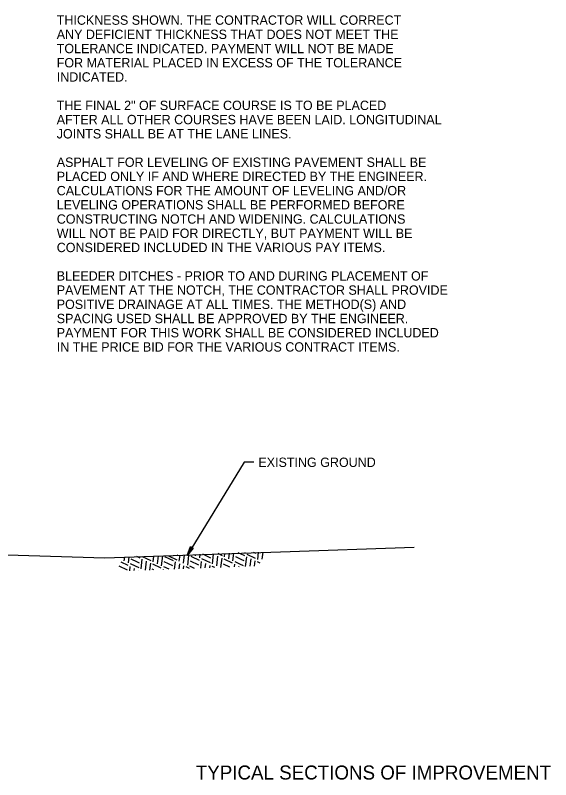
# Model space of a CAD drawing. Extents: x 1824008 to 1828864, y 689441 to 689870.
# Drawn here: x 1828827.02 to 1828861.38, y 689770.93 to 689820.02 of the extents above; entities that cross this region are included whole.
import ezdxf

# ---------------------------------------------------------------- set-up
doc = ezdxf.new("R2010")
doc.units = 0
for name, color, linetype in [('1', 7, 'Continuous'), ('19', 7, 'Continuous'), ('R_Draft', 7, 'Continuous')]:
    doc.layers.add(name, color=color, linetype=linetype)

msp = doc.modelspace()

# ---------------------------------------------------------------- linework, layer by layer
at = {"layer": '1'}
for p, q in [((1828839.673, 689784.783), (1828839.749, 689785.411)), ((1828839.673, 689784.783), (1828839.749, 689785.411)), ((1828840.31, 689785.311), (1828840.03, 689785.444)), ((1828840.31, 689785.311), (1828840.03, 689785.444)), ((1828840.31, 689785.311), (1828840.03, 689785.444)), ((1828840.446, 689785.247), (1828840.472, 689785.46)), ((1828840.446, 689785.247), (1828840.472, 689785.46)), ((1828840.446, 689785.247), (1828840.472, 689785.46)), ((1828840.717, 689785.118), (1828840.76, 689785.471)), ((1828840.717, 689785.118), (1828840.76, 689785.471)), ((1828840.717, 689785.118), (1828840.76, 689785.471)), ((1828840.988, 689784.99), (1828841.048, 689785.481)), ((1828840.988, 689784.99), (1828841.048, 689785.481)), ((1828840.988, 689784.99), (1828841.048, 689785.481)), ((1828841.697, 689785.318), (1828841.331, 689785.492)), ((1828841.697, 689785.318), (1828841.331, 689785.492)), ((1828841.697, 689785.318), (1828841.331, 689785.492)), ((1828841.761, 689785.454), (1828841.768, 689785.508)), ((1828841.761, 689785.454), (1828841.768, 689785.508)), ((1828841.761, 689785.454), (1828841.768, 689785.508)), ((1828842.477, 689785.447), (1828842.306, 689785.528)), ((1828842.477, 689785.447), (1828842.306, 689785.528)), ((1828842.477, 689785.447), (1828842.306, 689785.528)), ((1828842.574, 689785.069), (1828842.631, 689785.54)), ((1828842.574, 689785.069), (1828842.631, 689785.54)), ((1828842.574, 689785.069), (1828842.631, 689785.54)), ((1828842.863, 689785.086), (1828842.919, 689785.55)), ((1828842.863, 689785.086), (1828842.919, 689785.55)), ((1828842.863, 689785.086), (1828842.919, 689785.55)), ((1828834.01, 689784.976), (1828834.04, 689785.222)), ((1828834.01, 689784.976), (1828834.04, 689785.222)), ((1828834.01, 689784.976), (1828834.04, 689785.222)), ((1828834.281, 689784.847), (1828834.328, 689785.233)), ((1828834.281, 689784.847), (1828834.328, 689785.233)), ((1828834.281, 689784.847), (1828834.328, 689785.233)), ((1828834.862, 689784.904), (1828834.455, 689785.097)), ((1828834.862, 689784.904), (1828834.455, 689785.097)), ((1828834.862, 689784.904), (1828834.455, 689785.097)), ((1828834.99, 689785.176), (1828834.83, 689785.252)), ((1828834.99, 689785.176), (1828834.83, 689785.252)), ((1828834.99, 689785.176), (1828834.83, 689785.252)), ((1828835.035, 689785.154), (1828834.99, 689785.176)), ((1828835.035, 689785.154), (1828834.99, 689785.176)), ((1828835.035, 689785.154), (1828834.99, 689785.176)), ((1828835.095, 689784.462), (1828835.171, 689785.09)), ((1828835.095, 689784.462), (1828835.171, 689785.09)), ((1828835.095, 689784.462), (1828835.171, 689785.09)), ((1828835.732, 689784.99), (1828835.19, 689785.247)), ((1828835.732, 689784.99), (1828835.19, 689785.247)), ((1828835.732, 689784.99), (1828835.19, 689785.247)), ((1828835.372, 689784.384), (1828835.442, 689784.962)), ((1828835.372, 689784.384), (1828835.442, 689784.962)), ((1828835.372, 689784.384), (1828835.442, 689784.962)), ((1828835.868, 689784.926), (1828835.912, 689785.292)), ((1828835.868, 689784.926), (1828835.912, 689785.292)), ((1828835.868, 689784.926), (1828835.912, 689785.292)), ((1828836.139, 689784.797), (1828836.2, 689785.302)), ((1828836.139, 689784.797), (1828836.2, 689785.302)), ((1828836.139, 689784.797), (1828836.2, 689785.302)), ((1828836.41, 689784.669), (1828836.486, 689785.297)), ((1828836.41, 689784.669), (1828836.486, 689785.297)), ((1828836.41, 689784.669), (1828836.486, 689785.297)), ((1828837.164, 689784.976), (1828836.622, 689785.233)), ((1828837.164, 689784.976), (1828836.622, 689785.233)), ((1828837.164, 689784.976), (1828836.622, 689785.233)), ((1828837.409, 689785.026), (1828836.867, 689785.283)), ((1828837.409, 689785.026), (1828836.867, 689785.283)), ((1828837.409, 689785.026), (1828836.867, 689785.283)), ((1828837.447, 689785.34), (1828837.43, 689785.348)), ((1828837.447, 689785.34), (1828837.43, 689785.348)), ((1828837.447, 689785.34), (1828837.43, 689785.348)), ((1828837.544, 689784.962), (1828837.592, 689785.354)), ((1828837.544, 689784.962), (1828837.592, 689785.354)), ((1828837.544, 689784.962), (1828837.592, 689785.354)), ((1828837.815, 689784.833), (1828837.88, 689785.364)), ((1828837.815, 689784.833), (1828837.88, 689785.364)), ((1828837.815, 689784.833), (1828837.88, 689785.364)), ((1828838.087, 689784.705), (1828838.163, 689785.333)), ((1828838.087, 689784.705), (1828838.163, 689785.333)), ((1828838.087, 689784.705), (1828838.163, 689785.333)), ((1828838.802, 689784.698), (1828838.26, 689784.954)), ((1828838.802, 689784.698), (1828838.26, 689784.954)), ((1828838.802, 689784.698), (1828838.26, 689784.954)), ((1828838.343, 689785.247), (1828838.298, 689785.268)), ((1828838.343, 689785.247), (1828838.298, 689785.268)), ((1828838.343, 689785.247), (1828838.298, 689785.268)), ((1828838.84, 689785.011), (1828838.343, 689785.247)), ((1828838.84, 689785.011), (1828838.343, 689785.247)), ((1828838.84, 689785.011), (1828838.343, 689785.247)), ((1828838.588, 689785.297), (1828838.6, 689785.391)), ((1828838.588, 689785.297), (1828838.6, 689785.391)), ((1828838.588, 689785.297), (1828838.6, 689785.391)), ((1828838.859, 689785.168), (1828838.888, 689785.401)), ((1828838.859, 689785.168), (1828838.888, 689785.401)), ((1828838.859, 689785.168), (1828838.888, 689785.401)), ((1828838.924, 689784.515), (1828838.976, 689784.947)), ((1828838.924, 689784.515), (1828838.976, 689784.947)), ((1828838.924, 689784.515), (1828838.976, 689784.947)), ((1828839.537, 689784.847), (1828838.995, 689785.104)), ((1828839.537, 689784.847), (1828838.995, 689785.104)), ((1828839.537, 689784.847), (1828838.995, 689785.104)), ((1828839.575, 689785.161), (1828839.055, 689785.408)), ((1828839.575, 689785.161), (1828839.055, 689785.408)), ((1828839.575, 689785.161), (1828839.055, 689785.408)), ((1828839.944, 689784.655), (1828840.02, 689785.283)), ((1828839.944, 689784.655), (1828840.02, 689785.283)), ((1828839.944, 689784.655), (1828840.02, 689785.283)), ((1828840.22, 689784.563), (1828840.291, 689785.154)), ((1828840.22, 689784.563), (1828840.291, 689785.154)), ((1828840.22, 689784.563), (1828840.291, 689785.154)), ((1828840.969, 689784.833), (1828840.427, 689785.09)), ((1828840.969, 689784.833), (1828840.427, 689785.09)), ((1828840.969, 689784.833), (1828840.427, 689785.09)), ((1828841.44, 689784.776), (1828841.124, 689784.926)), ((1828841.44, 689784.776), (1828841.124, 689784.926)), ((1828841.44, 689784.776), (1828841.124, 689784.926)), ((1828841.568, 689785.047), (1828841.162, 689785.24)), ((1828841.568, 689785.047), (1828841.162, 689785.24)), ((1828841.568, 689785.047), (1828841.162, 689785.24)), ((1828841.704, 689784.983), (1828841.568, 689785.047)), ((1828841.704, 689784.983), (1828841.568, 689785.047)), ((1828841.704, 689784.983), (1828841.568, 689785.047)), ((1828841.742, 689785.297), (1828841.697, 689785.318)), ((1828841.742, 689785.297), (1828841.697, 689785.318)), ((1828841.742, 689785.297), (1828841.697, 689785.318)), ((1828841.803, 689784.621), (1828841.878, 689785.233)), ((1828841.803, 689784.621), (1828841.878, 689785.233)), ((1828841.803, 689784.621), (1828841.878, 689785.233)), ((1828842.439, 689785.133), (1828841.897, 689785.39)), ((1828842.439, 689785.133), (1828841.897, 689785.39)), ((1828842.439, 689785.133), (1828841.897, 689785.39)), ((1828842.091, 689784.632), (1828842.149, 689785.104)), ((1828842.091, 689784.632), (1828842.149, 689785.104)), ((1828842.091, 689784.632), (1828842.149, 689785.104)), ((1828842.379, 689784.642), (1828842.42, 689784.976)), ((1828842.379, 689784.642), (1828842.42, 689784.976)), ((1828842.379, 689784.642), (1828842.42, 689784.976)), ((1828834.224, 689784.376), (1828833.686, 689784.631)), ((1828834.224, 689784.376), (1828833.686, 689784.631)), ((1828834.224, 689784.376), (1828833.686, 689784.631)), ((1828834.262, 689784.69), (1828833.815, 689784.902)), ((1828834.262, 689784.69), (1828833.815, 689784.902)), ((1828834.262, 689784.69), (1828833.815, 689784.902)), ((1828834.364, 689784.346), (1828834.398, 689784.626)), ((1828834.364, 689784.346), (1828834.398, 689784.626)), ((1828834.364, 689784.346), (1828834.398, 689784.626)), ((1828834.733, 689784.633), (1828834.417, 689784.783)), ((1828834.733, 689784.633), (1828834.417, 689784.783)), ((1828834.733, 689784.633), (1828834.417, 689784.783)), ((1828834.652, 689784.357), (1828834.669, 689784.498)), ((1828834.652, 689784.357), (1828834.669, 689784.498)), ((1828834.652, 689784.357), (1828834.669, 689784.498)), ((1828834.959, 689784.526), (1828834.733, 689784.633)), ((1828834.959, 689784.526), (1828834.733, 689784.633)), ((1828834.959, 689784.526), (1828834.733, 689784.633)), ((1828834.997, 689784.84), (1828834.862, 689784.904)), ((1828834.997, 689784.84), (1828834.862, 689784.904)), ((1828834.997, 689784.84), (1828834.862, 689784.904)), ((1828835.66, 689784.394), (1828835.713, 689784.833)), ((1828835.66, 689784.394), (1828835.713, 689784.833)), ((1828835.66, 689784.394), (1828835.713, 689784.833)), ((1828835.918, 689784.404), (1828835.811, 689784.455)), ((1828835.918, 689784.404), (1828835.811, 689784.455)), ((1828835.918, 689784.404), (1828835.811, 689784.455)), ((1828836.391, 689784.512), (1828835.849, 689784.769)), ((1828836.391, 689784.512), (1828835.849, 689784.769)), ((1828836.391, 689784.512), (1828835.849, 689784.769)), ((1828836.524, 689784.426), (1828836.526, 689784.448)), ((1828836.524, 689784.426), (1828836.526, 689784.448)), ((1828836.524, 689784.426), (1828836.526, 689784.448)), ((1828836.894, 689784.44), (1828836.545, 689784.605)), ((1828836.894, 689784.44), (1828836.545, 689784.605)), ((1828836.894, 689784.44), (1828836.545, 689784.605)), ((1828837.126, 689784.662), (1828836.583, 689784.919)), ((1828837.126, 689784.662), (1828836.583, 689784.919)), ((1828837.126, 689784.662), (1828836.583, 689784.919)), ((1828837.244, 689784.453), (1828837.299, 689784.912)), ((1828837.244, 689784.453), (1828837.299, 689784.912)), ((1828837.244, 689784.453), (1828837.299, 689784.912)), ((1828837.532, 689784.463), (1828837.57, 689784.783)), ((1828837.532, 689784.463), (1828837.57, 689784.783)), ((1828837.532, 689784.463), (1828837.57, 689784.783)), ((1828837.82, 689784.474), (1828837.842, 689784.655)), ((1828837.82, 689784.474), (1828837.842, 689784.655)), ((1828837.82, 689784.474), (1828837.842, 689784.655)), ((1828838.022, 689784.569), (1828837.977, 689784.591)), ((1828838.022, 689784.569), (1828837.977, 689784.591)), ((1828838.022, 689784.569), (1828837.977, 689784.591)), ((1828838.194, 689784.488), (1828838.022, 689784.569)), ((1828838.194, 689784.488), (1828838.022, 689784.569)), ((1828838.194, 689784.488), (1828838.022, 689784.569)), ((1828838.519, 689784.5), (1828838.222, 689784.64)), ((1828838.519, 689784.5), (1828838.222, 689784.64)), ((1828838.519, 689784.5), (1828838.222, 689784.64)), ((1828839.212, 689784.525), (1828839.247, 689784.819)), ((1828839.212, 689784.525), (1828839.247, 689784.819)), ((1828839.212, 689784.525), (1828839.247, 689784.819)), ((1828839.5, 689784.536), (1828839.518, 689784.69)), ((1828839.5, 689784.536), (1828839.518, 689784.69)), ((1828839.5, 689784.536), (1828839.518, 689784.69)), ((1828839.819, 689784.548), (1828839.654, 689784.626)), ((1828839.819, 689784.548), (1828839.654, 689784.626)), ((1828839.819, 689784.548), (1828839.654, 689784.626)), ((1828840.794, 689784.584), (1828840.389, 689784.776)), ((1828840.794, 689784.584), (1828840.389, 689784.776)), ((1828840.794, 689784.584), (1828840.389, 689784.776)), ((1828841.083, 689784.595), (1828841.105, 689784.769)), ((1828841.083, 689784.595), (1828841.105, 689784.769)), ((1828841.083, 689784.595), (1828841.105, 689784.769)), ((1828841.371, 689784.605), (1828841.376, 689784.64)), ((1828841.371, 689784.605), (1828841.376, 689784.64)), ((1828841.371, 689784.605), (1828841.376, 689784.64)), ((1828841.666, 689784.669), (1828841.44, 689784.776)), ((1828841.666, 689784.669), (1828841.44, 689784.776)), ((1828841.666, 689784.669), (1828841.44, 689784.776)), ((1828842.739, 689784.824), (1828842.555, 689784.912)), ((1828842.739, 689784.824), (1828842.555, 689784.912)), ((1828842.739, 689784.824), (1828842.555, 689784.912)), ((1828834.94, 689784.368), (1828834.94, 689784.369)), ((1828834.94, 689784.368), (1828834.94, 689784.369)), ((1828834.94, 689784.368), (1828834.94, 689784.369))]:
    msp.add_line(p, q, dxfattribs=at)
msp.add_lwpolyline([(1828852.627, 689785.831), (1828844.044, 689785.542), (1828832.759, 689785.156), (1828826.49, 689785.349), (1828820.607, 689784.963), (1828817.941, 689784.736)], dxfattribs=at)
at = {"layer": 'R_Draft'}
for p, q in [((1828838.042, 689785.336), (1828838.265, 689785.903)), ((1828838.265, 689785.903), (1828838.443, 689785.793)), ((1828838.443, 689785.793), (1828838.042, 689785.336)), ((1828838.116, 689785.477), (1828838.309, 689785.871)), ((1828838.402, 689785.815), (1828838.139, 689785.466)), ((1828839.673, 689784.783), (1828839.749, 689785.411)), ((1828840.31, 689785.311), (1828840.03, 689785.444)), ((1828840.446, 689785.247), (1828840.472, 689785.46)), ((1828840.717, 689785.118), (1828840.76, 689785.471)), ((1828840.988, 689784.99), (1828841.048, 689785.481)), ((1828841.697, 689785.318), (1828841.331, 689785.492)), ((1828841.761, 689785.454), (1828841.768, 689785.508)), ((1828842.477, 689785.447), (1828842.306, 689785.528)), ((1828842.574, 689785.069), (1828842.631, 689785.54)), ((1828842.863, 689785.086), (1828842.919, 689785.55)), ((1828834.01, 689784.976), (1828834.04, 689785.222)), ((1828834.281, 689784.847), (1828834.328, 689785.233)), ((1828834.862, 689784.904), (1828834.455, 689785.097)), ((1828834.99, 689785.176), (1828834.83, 689785.252)), ((1828835.035, 689785.154), (1828834.99, 689785.176)), ((1828835.095, 689784.462), (1828835.171, 689785.09)), ((1828835.732, 689784.99), (1828835.19, 689785.247)), ((1828835.372, 689784.384), (1828835.442, 689784.962)), ((1828835.868, 689784.926), (1828835.912, 689785.292)), ((1828836.139, 689784.797), (1828836.2, 689785.302)), ((1828836.41, 689784.669), (1828836.486, 689785.297)), ((1828837.164, 689784.976), (1828836.622, 689785.233)), ((1828837.409, 689785.026), (1828836.867, 689785.283)), ((1828837.447, 689785.34), (1828837.43, 689785.348)), ((1828837.544, 689784.962), (1828837.592, 689785.354)), ((1828837.815, 689784.833), (1828837.88, 689785.364)), ((1828838.087, 689784.705), (1828838.163, 689785.333)), ((1828838.802, 689784.698), (1828838.26, 689784.954)), ((1828838.343, 689785.247), (1828838.298, 689785.268)), ((1828838.84, 689785.011), (1828838.343, 689785.247)), ((1828838.588, 689785.297), (1828838.6, 689785.391)), ((1828838.859, 689785.168), (1828838.888, 689785.401)), ((1828838.924, 689784.515), (1828838.976, 689784.947)), ((1828839.537, 689784.847), (1828838.995, 689785.104)), ((1828839.575, 689785.161), (1828839.055, 689785.408)), ((1828839.944, 689784.655), (1828840.02, 689785.283)), ((1828840.22, 689784.563), (1828840.291, 689785.154)), ((1828840.969, 689784.833), (1828840.427, 689785.09)), ((1828841.44, 689784.776), (1828841.124, 689784.926)), ((1828841.568, 689785.047), (1828841.162, 689785.24)), ((1828841.704, 689784.983), (1828841.568, 689785.047)), ((1828841.742, 689785.297), (1828841.697, 689785.318)), ((1828841.803, 689784.621), (1828841.878, 689785.233)), ((1828842.439, 689785.133), (1828841.897, 689785.39)), ((1828842.091, 689784.632), (1828842.149, 689785.104)), ((1828842.379, 689784.642), (1828842.42, 689784.976)), ((1828834.224, 689784.376), (1828833.686, 689784.631)), ((1828834.262, 689784.69), (1828833.815, 689784.902)), ((1828834.364, 689784.346), (1828834.398, 689784.626)), ((1828834.733, 689784.633), (1828834.417, 689784.783)), ((1828834.652, 689784.357), (1828834.669, 689784.498)), ((1828834.959, 689784.526), (1828834.733, 689784.633)), ((1828834.997, 689784.84), (1828834.862, 689784.904)), ((1828835.66, 689784.394), (1828835.713, 689784.833)), ((1828835.918, 689784.404), (1828835.811, 689784.455)), ((1828836.391, 689784.512), (1828835.849, 689784.769)), ((1828836.524, 689784.426), (1828836.526, 689784.448)), ((1828836.894, 689784.44), (1828836.545, 689784.605)), ((1828837.126, 689784.662), (1828836.583, 689784.919)), ((1828837.244, 689784.453), (1828837.299, 689784.912)), ((1828837.532, 689784.463), (1828837.57, 689784.783)), ((1828837.82, 689784.474), (1828837.842, 689784.655)), ((1828838.022, 689784.569), (1828837.977, 689784.591)), ((1828838.194, 689784.488), (1828838.022, 689784.569)), ((1828838.519, 689784.5), (1828838.222, 689784.64)), ((1828839.212, 689784.525), (1828839.247, 689784.819)), ((1828839.5, 689784.536), (1828839.518, 689784.69)), ((1828839.819, 689784.548), (1828839.654, 689784.626)), ((1828840.794, 689784.584), (1828840.389, 689784.776)), ((1828841.083, 689784.595), (1828841.105, 689784.769)), ((1828841.371, 689784.605), (1828841.376, 689784.64)), ((1828841.666, 689784.669), (1828841.44, 689784.776)), ((1828842.739, 689784.824), (1828842.555, 689784.912)), ((1828834.94, 689784.368), (1828834.94, 689784.369))]:
    msp.add_line(p, q, dxfattribs=at)
msp.add_lwpolyline([(1828842.318, 689791.312), (1828841.718, 689791.312), (1828838.042, 689785.336)], dxfattribs=at)

# ---------------------------------------------------------------- texts
at = {"layer": '19'}
for s, p in [('THICKNESS SHOWN. THE CONTRACTOR WILL CORRECT', (1828829.679, 689819.406)), ('ANY DEFICIENT THICKNESS THAT DOES NOT MEET THE', (1828829.679, 689818.494)), ('TOLERANCE INDICATED. PAYMENT WILL NOT BE MADE', (1828829.679, 689817.581)), ('FOR MATERIAL PLACED IN EXCESS OF THE TOLERANCE', (1828829.679, 689816.669)), ('INDICATED.', (1828829.679, 689815.756)), ('THE FINAL 2" OF SURFACE COURSE IS TO BE PLACED', (1828829.679, 689813.931)), ('AFTER ALL OTHER COURSES HAVE BEEN LAID. LONGITUDINAL', (1828829.679, 689813.019)), ('JOINTS SHALL BE AT THE LANE LINES.', (1828829.679, 689812.106)), ('ASPHALT FOR LEVELING OF EXISTING PAVEMENT SHALL BE', (1828829.679, 689810.281)), ('PLACED ONLY IF AND WHERE DIRECTED BY THE ENGINEER.', (1828829.679, 689809.369)), ('CALCULATIONS FOR THE AMOUNT OF LEVELING AND/OR', (1828829.679, 689808.456)), ('LEVELING OPERATIONS SHALL BE PERFORMED BEFORE ', (1828829.679, 689807.544)), ('CONSTRUCTING NOTCH AND WIDENING. CALCULATIONS', (1828829.679, 689806.631)), ('WILL NOT BE PAID FOR DIRECTLY, BUT PAYMENT WILL BE', (1828829.679, 689805.719)), ('CONSIDERED INCLUDED IN THE VARIOUS PAY ITEMS.', (1828829.679, 689804.806)), ('BLEEDER DITCHES - PRIOR TO AND DURING PLACEMENT OF ', (1828829.679, 689802.981)), ('PAVEMENT AT THE NOTCH, THE CONTRACTOR SHALL PROVIDE ', (1828829.679, 689802.069)), ('POSITIVE DRAINAGE AT ALL TIMES. THE METHOD(S) AND ', (1828829.679, 689801.156)), ('SPACING USED SHALL BE APPROVED BY THE ENGINEER. ', (1828829.679, 689800.244)), ('PAYMENT FOR THIS WORK SHALL BE CONSIDERED INCLUDED ', (1828829.679, 689799.331)), ('IN THE PRICE BID FOR THE VARIOUS CONTRACT ITEMS.', (1828829.679, 689798.419))]:
    msp.add_text(s, height=0.6, dxfattribs=at).set_placement(p)
at = {"layer": 'R_Draft'}
for s, height, p in [('EXISTING GROUND', 0.6, (1828842.618, 689791.012)), ('TYPICAL SECTIONS OF IMPROVEMENT', 0.9, (1828838.604, 689770.94))]:
    msp.add_text(s, height=height, dxfattribs=at).set_placement(p)

doc.saveas('drawing.dxf')
